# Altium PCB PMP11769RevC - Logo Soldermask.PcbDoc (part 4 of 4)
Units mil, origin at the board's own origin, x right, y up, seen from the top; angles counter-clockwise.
Board outline 7800 x 8510 mil, 4 copper layers (Top, Inner Top, Inner Bottom, Bottom), stack 33.235 mil thick; 451 components, 226 nets, 1199 pads, 1742 vias.
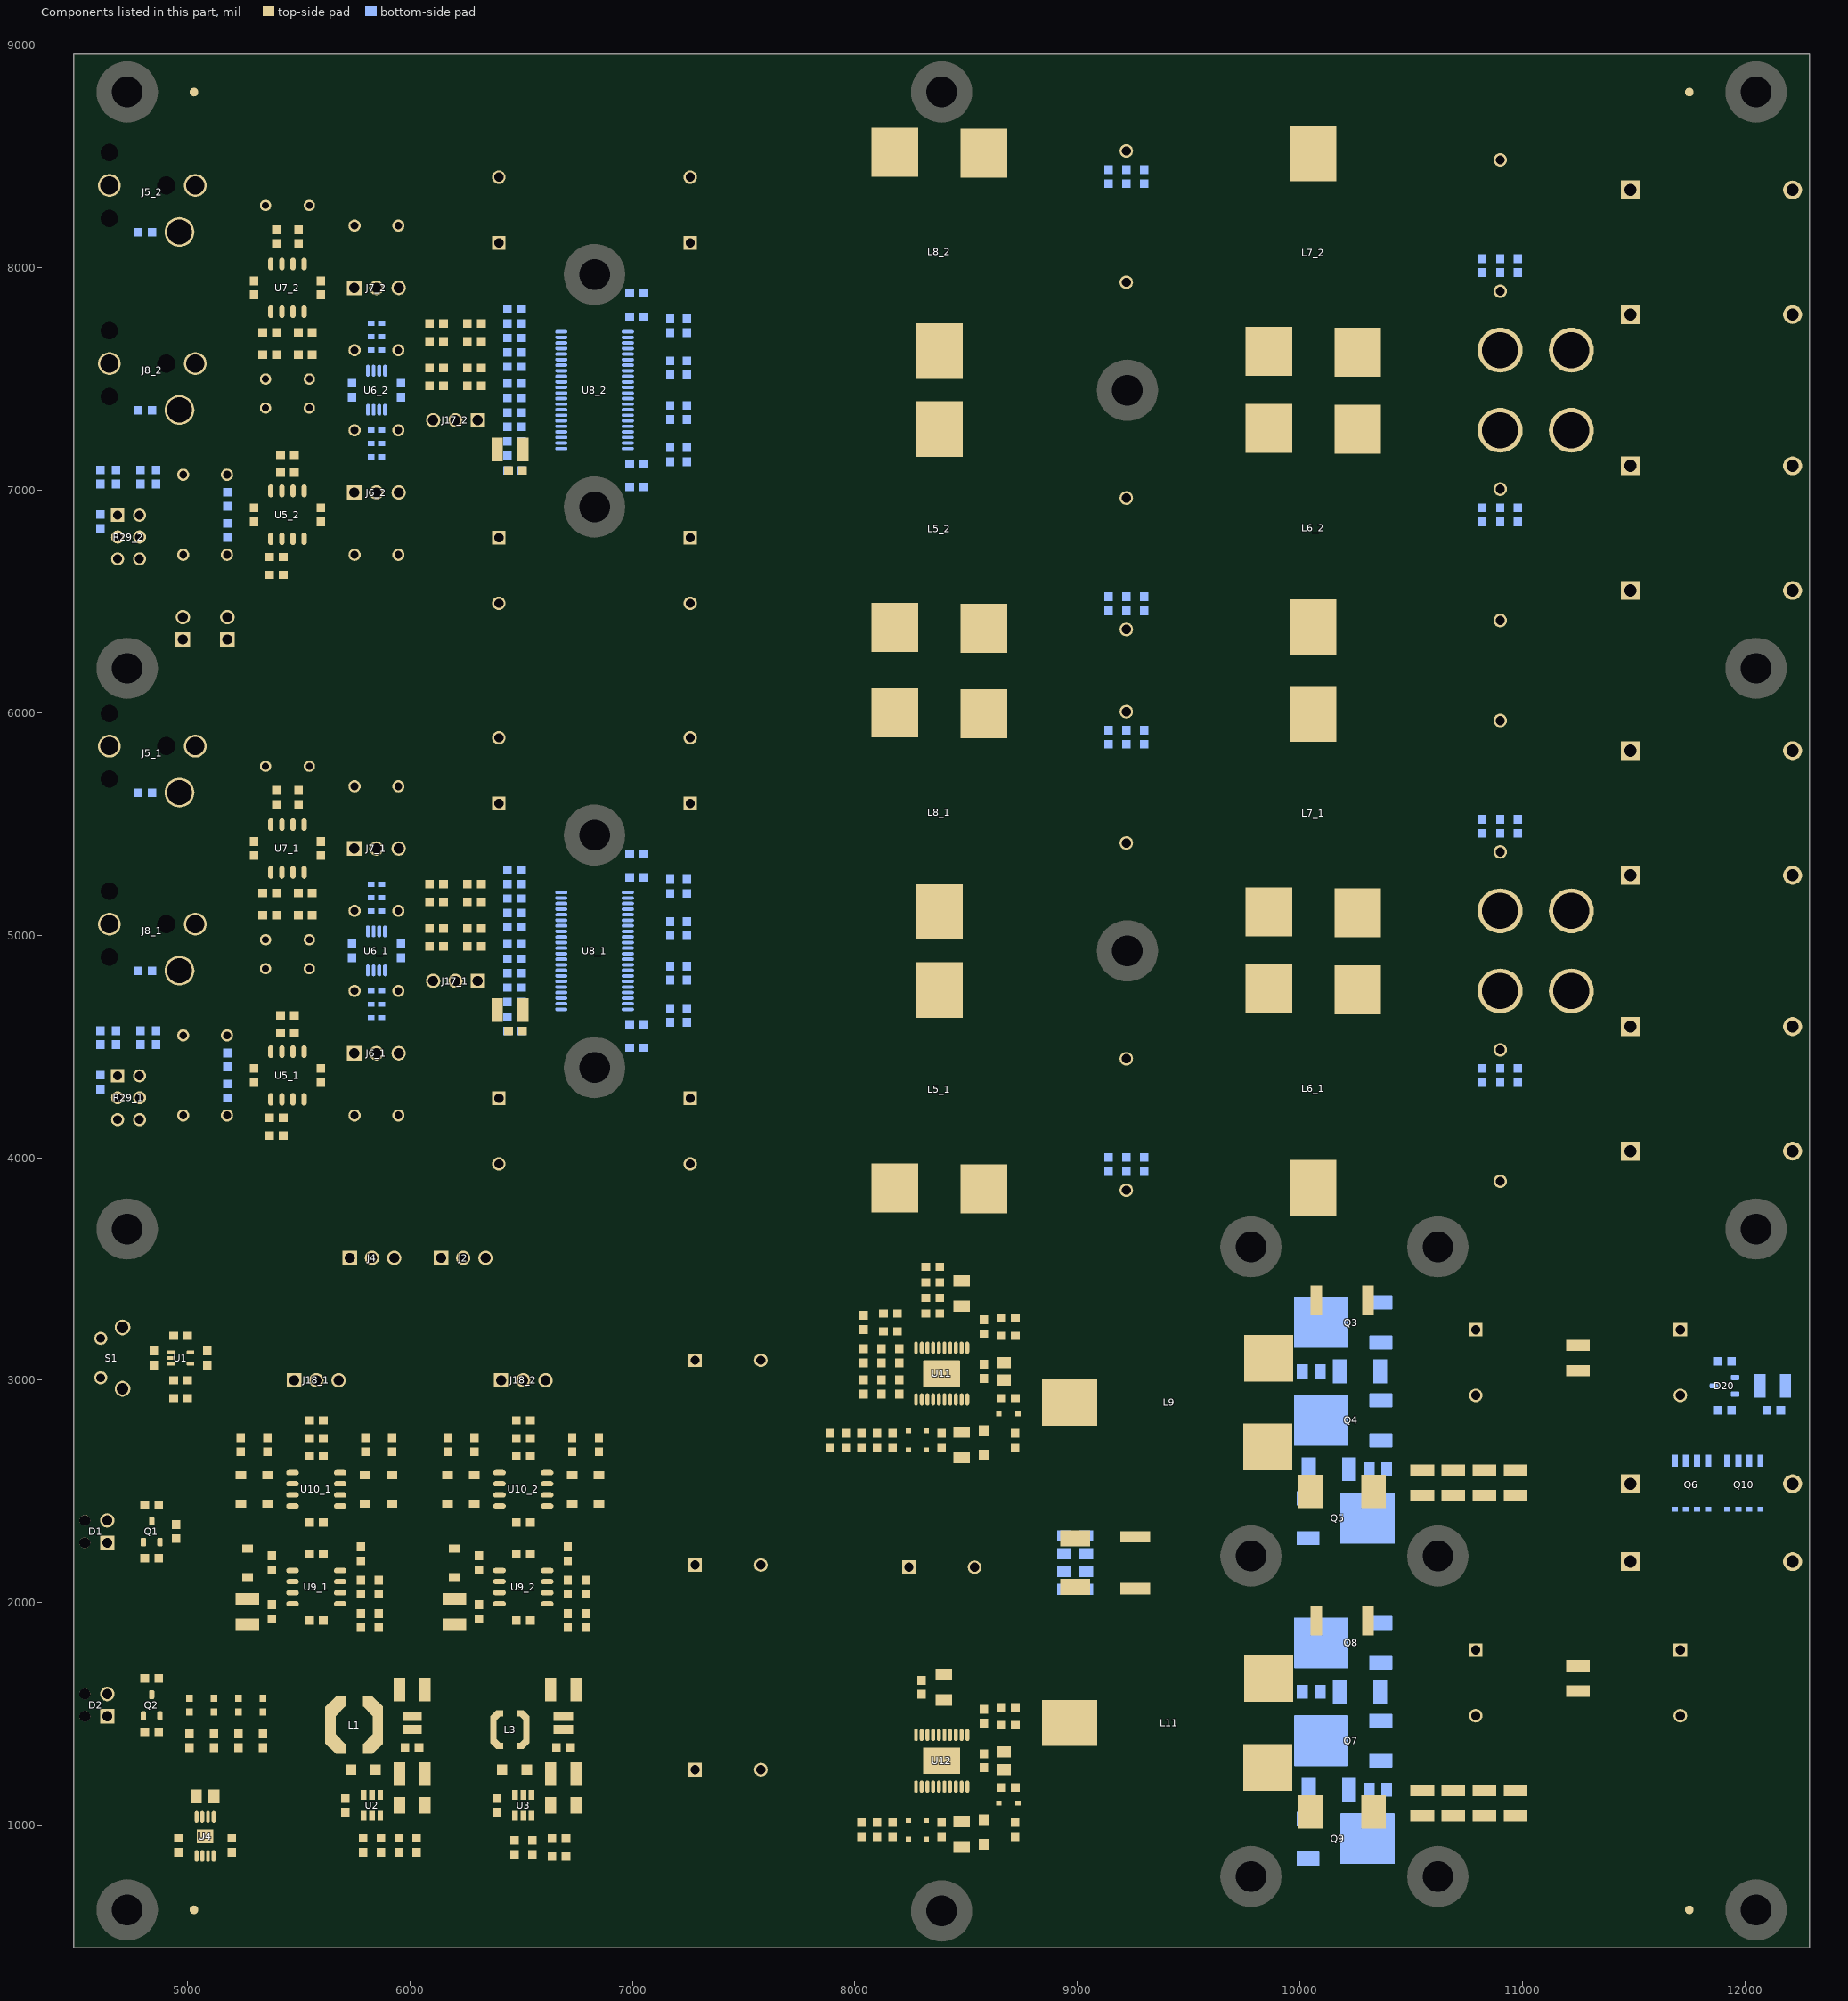
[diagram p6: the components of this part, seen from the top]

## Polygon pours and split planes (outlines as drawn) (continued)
+3V3 on Top "Top-No Net 24" (solid, pour order 446): 5050,1010 4990,1010 4990,1185 5070,1185 5070,1095 5050,1075
NetC16_1 on Top "Top-No Net 23" (solid, pour order 445): 5245,900 5110,900 5110,815 5245,815
+12V on Top "Top-No Net 23" (solid, pour order 447): 5075,900 4915,900 4915,815 5075,815
PVDD on Top "Top-No Net 22" (solid, pour order 513): 7050,3600 7810,3600 7810,770 7050,770
PVDD on Top "Top-No Net 22" (solid, pour order 498): 8810,2520 8810,1800 7200,1800 7200,2520
PVDD on Top "Top-No Net 21" (solid, pour order 461): 9590,2160 9590,2030 8790,2030 8790,2160
NetC95_2 on Top "Top-No Net 20" (solid, pour order 467): 8850,2200 9590,2200 9590,2440 8850,2440
GND on Top "Top-No Net 19" (solid, pour order 468): 11100,2200 11100,2070 9700,2070 9700,2200
GND on Top "Bottom-No Net 24" (solid, pour order 508): 7850,2560 7850,3600 9590,3600 9590,2560
VIN on Top "Top-No Net 14" (solid, pour order 493): 11890,3470 12290,3470 12290,1680 11890,1680
NetL11_2 on Top "Top-No Net 9" (solid, pour order 474): 10170,2030 9700,2030 9700,1520 10170,1520
SW-2 on Top "Top-No Net 10" (solid, pour order 484): 10170,1480 9700,1480 9700,770 10170,770
SW-1 on Top "Top-No Net 10" (solid, pour order 483): 10170,2920 9700,2920 9700,2240 10170,2240
NetL9_2 on Top "Top-No Net 9" (solid, pour order 473): 10170,3430 9700,3430 9700,2960 10170,2960
VIN on Top "Top-No Net 8" (solid, pour order 496): 12290,3600 12290,3120 10220,3120 10220,3600
NetC68_1_1 on Top "Bottom-No Net" (solid, remove dead copper, pour order 499): 12290,4950 12290,5530 10080,5530 10080,4950
NetC74_1_1 on Top "Bottom-No Net 1" (solid, remove dead copper, pour order 511): 12290,6120 8400,6120 8400,5570 12290,5570
NetC61_1_1 on Top "Bottom-No Net" (solid, remove dead copper, pour order 500): 12290,4330 12290,4910 10080,4910 10080,4330
NetC41_1_1 on Top "Bottom-No Net 1" (solid, remove dead copper, pour order 509): 12290,3750 8400,3750 8400,4290 12290,4290
NetC55_1_2 on Top "Top-No Net 2" (solid, remove dead copper, pour order 486): 8360,3750 7640,3750 7640,4290 8360,4290
NetC65_1_1 on Top "Top-No Net 2" (solid, remove dead copper, pour order 488): 8360,5570 7640,5570 7640,6120 8360,6120
NetC64_1_1 on Top "Top-No Net 3" (solid, remove dead copper, pour order 503): 7690,4950 10040,4950 10040,5530 7690,5530
NetC54_1_2 on Top "Top-No Net 3" (solid, remove dead copper, pour order 504): 7690,4330 10040,4330 10040,4910 7690,4910
NetC64_1_1 on Top "Top-No Net" (solid, remove dead copper, pour order 437): 7030,5000 7020,4990 7020,4950 7030,4940 7100,4940 7100,5000
NetC54_1_2 on Top "Top-No Net" (solid, remove dead copper, pour order 439): 7030,4920 7020,4910 7020,4870 7030,4860 7100,4860 7100,4920
NetC64_1_1 on Top "Top-No Net 4" (solid, pour order 469): 7095,5000 7105,5000 7125,5000 7655,5530 7695,5530 7695,4950 7125,4950 7115,4940 7095,4940
NetC54_1_2 on Top "Top-No Net 4" (solid, pour order 471): 7095,4860 7105,4860 7125,4860 7655,4330 7695,4330 7695,4910 7125,4910 7115,4920 7095,4920
NetC65_1_1 on Top "Top-No Net 6" (solid, pour order 480): 7090,5050 7125,5050 7645,5570 7645,6120 7320,6120 7320,5550 7090,5320
NetC55_1_2 on Top "Top-No Net 6" (solid, pour order 479): 7090,4810 7125,4810 7645,4290 7645,3750 7320,3750 7320,4310 7090,4540
NetC55_1_2 on Top "Top-No Net 1" (solid, pour order 451): 7020,4810 7020,4530 7100,4530 7100,4810
NetC65_1_1 on Top "Top-No Net 1" (solid, pour order 450): 7020,5330 7020,5050 7100,5050 7100,5330
GND on Top "Top-No Net 5" (solid, pour order 492): 6045,5750 6045,6120 7295,6120 7295,5750
GND on Top "Top-No Net 5" (solid, pour order 490): 6045,3750 6045,4110 7295,4110 7295,3750
GND on Top "Top-No Net 7" (solid, remove dead copper, pour order 515): 4490,6120 4490,3750 6325,3750 6325,4340 6942.5,4340 6942.5,5515 6325,5515 6325,6120
NetC95_2 on Top "Top-No Net 11" (solid, pour order 475): 11040,2240 11040,2520 10450,2520 10450,2600 10220,2600 10220,2240
VIN on Top "Top-No Net 8" (solid, pour order 494): 12285,2030 12285,1680 10220,1680 10220,2030
GND on Top "Top-No Net 12" (solid, pour order 497): 10220,1640 10220,1200 10470,1200 10470,1120 12290,1120 12290,1640
NetC95_2 on Top "Top-No Net 11" (solid, pour order 476): 11040,770 11040,1080 10450,1080 10450,1160 10220,1160 10220,770
GND on Top "Top-No Net 15" (solid, pour order 495): 10220,3080 10220,2640 10470,2640 10470,2560 11330,2560 11330,2620 11870,2620 11870,3080
GND on Top "Bottom-No Net 24" (solid, pour order 507): 7850,770 7850,1760 9590,1760 9590,770
GND on Top "Top-No Net 16" (solid, pour order 477): 11080,770 11080,1140 12290,1140 12290,1030 11710,1030 11710,770
VIN on Top "Top-No Net 17" (solid, pour order 460): 10240,3600 10240,3440 9700,3440 9700,3600
GND on Top "Top-No Net 18" (solid, pour order 462): 11080,2620 11080,2070 11330,2070 11330,2620
VIN on Top "Top-No Net 13" (solid, pour order 482): 11360,2580 11910,2580 11910,2010 11360,2010
VIN on Bottom "Bottom-No Net 5" (solid, pour order 621): 12130,2830 11990,2830 11990,3050 12130,3050
PVDD on Bottom "Bottom-No Net 2" (solid, remove dead copper, pour order 625): 6950,7508.7 7020,7508.7 7031.3,7520 7115,7520 7150,7555 7320,7555 7320,7735 7125,7735 7125,7700 7125,7603.7 7091.3,7570 6950,7570
GND on Bottom "Bottom-No Net 11" (solid, remove dead copper, pour order 647): 6025,8640 7335,8638.89 7335,6270 4490,6270 4490,8640
GND on Bottom "Bottom-No Net 9" (solid, remove dead copper, pour order 651): 7315,8640 7315,6270 12290,6270 12290,8640
PVDD on Bottom "Bottom-No Net 2" (solid, remove dead copper, pour order 626): 6950,7395 7015,7395 7030,7380 7120,7380 7155,7345 7320,7345 7320,7165 7125,7165 7125,7200 7125,7295 7090,7330 6950,7330
NetC64_2_1 on Bottom "Bottom-No Net 3" (solid, remove dead copper, pour order 603): 6950,7495 6950,7480 7025,7480 7035,7470 7090,7470 7100,7480 7100,7500 7090,7510 7035,7510 7020,7495
NetC54_2_2 on Bottom "Bottom-No Net 3" (solid, remove dead copper, pour order 602): 6950,7405 6950,7420 7025,7420 7035,7430 7090,7430 7100,7420 7100,7400 7090,7390 7036.04,7390 7021.04,7405
NetC55_2_2 on Bottom "Bottom-No Net 4" (solid, remove dead copper, pour order 605): 6950,7320 6950,7280 7087.5,7280 7097.5,7290 7097.5,7310 7087.5,7320
NetC65_2_1 on Bottom "Bottom-No Net 4" (solid, remove dead copper, pour order 608): 6950,7620 6950,7580 7087.5,7580 7097.5,7590 7097.5,7610 7087.5,7620
PVDD on Bottom "Bottom-No Net 31" (solid, pour order 623): 8805,2025 8805,2160 8885,2160 8885,2105 8900,2090 9080,2090 9093.07,2101.58 9095,2105 9095,2100 9095,2160 9175,2160 9175,2025
NetC95_2 on Bottom "Bottom-No Net 30" (solid, pour order 622): 9085,2270 8890,2270 8890,2425 9090,2425 9090,2270
GND on Bottom "Bottom-No Net 29" (solid, pour order 628): 5380,3580 5380,3770 5655,3770 5660,3775 5660,3580
GND on Bottom "Top-No Net 34" (solid, pour order 649): 4490,3600 7010,3600 7010,770 4490,770
NetC10_2 on Bottom "Bottom-No Net 28" (solid, pour order 629): 6450,960 6600,960 6600,1315 6450,1315
GND on Bottom "Bottom-No Net 27" (solid, pour order 638): 7930,6310 6050,6310 6050,6080 7930,6080
GND on Bottom "Bottom-No Net 24" (solid, pour order 645): 7850,2500 7850,3600 9660,3600 9660,2500
GND on Bottom "Bottom-No Net 20" (solid, pour order 644): 12290,2600 10470,2600 10470,2690 10300,2690 10300,3600 12290,3600
NetJ20_1 on Bottom "Bottom-No Net 19" (solid, pour order 631): 12290,2580 12290,2350 11425,2350 11425,2580
NetD17_2 on Bottom "Bottom-No Net 18" (solid, pour order 613): 10460,3390 10460,3310 10300,3310 10300,3390
NetD18_2 on Bottom "Bottom-No Net 18" (solid, pour order 612): 10460,2950 10460,2870 10300,2870 10300,2950
NetD19_2 on Bottom "Bottom-No Net 18" (solid, pour order 611): 10100,2330 10100,2250 9940,2250 9940,2330
NetC111_1 on Bottom "Bottom-No Net 14" (solid, pour order 619): 10340,1100 10180,1100 10180,1220 10340,1220
NetC95_2 on Bottom "Bottom-No Net 17" (solid, pour order 615): 10360,1220 10450,1220 10450,1060 10360,1060
NetC116_2 on Bottom "Bottom-No Net 14" (solid, pour order 618): 10220,1550 10060,1550 10060,1670 10220,1670
NetC95_1 on Bottom "Bottom-No Net 14" (solid, pour order 620): 10340,2540 10160,2540 10160,2660 10340,2660
NetC96_2 on Bottom "Bottom-No Net 14" (solid, pour order 617): 10220,2980 10060,2980 10060,3100 10220,3100
NetC65_1_1 on Bottom "Bottom-No Net 4" (solid, remove dead copper, pour order 607): 6950,5100 6950,5060 7087.5,5060 7097.5,5070 7097.5,5090 7087.5,5100
NetC55_1_2 on Bottom "Bottom-No Net 4" (solid, remove dead copper, pour order 606): 6950,4800 6950,4760 7087.5,4760 7097.5,4770 7097.5,4790 7087.5,4800
NetC54_1_2 on Bottom "Bottom-No Net 3" (solid, remove dead copper, pour order 601): 6950,4885 6950,4900 7025,4900 7035,4910 7090,4910 7100,4900 7100,4880 7090,4870 7036.04,4870 7021.04,4885
NetC64_1_1 on Bottom "Bottom-No Net 3" (solid, remove dead copper, pour order 604): 6950,4975 6950,4960 7025,4960 7035,4950 7090,4950 7100,4960 7100,4980 7090,4990 7035,4990 7020,4975
PVDD on Bottom "Bottom-No Net 2" (solid, remove dead copper, pour order 627): 6950,4875 7015,4875 7030,4860 7115,4860 7150,4825 7320,4825 7320,4645 7125,4645 7125,4680 7125,4775 7090,4810 6950,4810
GND on Bottom "Bottom-No Net 9" (solid, remove dead copper, pour order 650): 7315,6120 7315,3750 12290,3750 12290,6120
GND on Bottom "Bottom-No Net 11" (solid, remove dead copper, pour order 648): 6025,6120 7335,6118.89 7335,3750 4490,3750 4490,6120
SW-1 on Bottom "Bottom-No Net 15" (solid, pour order 640): 10270,3470 10270,2690 10120,2690 10120,2240 9700,2240 9700,3470
NetC95_2 on Bottom "Bottom-No Net 16" (solid, pour order 633): 10160,2240 11040,2240 11040,2520 10160,2520
NetC95_2 on Bottom "Bottom-No Net 17" (solid, pour order 616): 10360,2660 10450,2660 10450,2500 10360,2500
NetC95_2 on Bottom "Bottom-No Net 16" (solid, pour order 635): 10160,770 11040,770 11040,1080 10160,1080
NetD24_2 on Bottom "Bottom-No Net 18" (solid, pour order 614): 10100,890 10100,810 9940,810 9940,890
SW-2 on Bottom "Bottom-No Net 15" (solid, pour order 639): 10270,1940 10270,1250 10120,1250 10120,770 9700,770 9700,1940
NetD23_2 on Bottom "Bottom-No Net 18" (solid, pour order 610): 10460,1950 10460,1870 10300,1870 10300,1950
NetD22_2 on Bottom "Bottom-No Net 18" (solid, pour order 609): 10460,1510 10460,1430 10300,1430 10300,1510
GND on Bottom "Bottom-No Net 20" (solid, pour order 641): 12290,1120 10470,1120 10470,1250 10300,1250 10300,2010 12290,2010
GND on Bottom "Bottom-No Net 21" (solid, pour order 632): 11400,2620 11060,2620 11060,1990 11400,1990
GND on Bottom "Bottom-No Net 23" (solid, pour order 637): 11080,2220 11080,1980 9620,1980 9620,2220
GND on Bottom "Bottom-No Net 24" (solid, pour order 643): 7850,770 7850,1820 9660,1820 9660,770
GND on Bottom "Bottom-No Net 25" (solid, pour order 630): 10330,3500 9700,3500 9700,3600 10330,3600
GND on Bottom "Bottom-No Net 25" (solid, pour order 636): 11710,770 11080,770 11080,1140 12290,1140 12290,1030 11710,1030
GND on Bottom "Bottom-No Net 26" (solid, pour order 642): 9660,2520 9660,1800 7200,1800 7200,2520
GND on Bottom "Bottom-No Net 27" (solid, pour order 646): 7810,3790 7050,3790 7050,770 7810,770
PVDD on Bottom "Bottom-No Net 2" (solid, remove dead copper, pour order 624): 6950,4988.7 7020,4988.7 7031.3,5000 7115,5000 7150,5035 7320,5035 7320,5215 7125,5215 7125,5180 7125,5083.7 7091.3,5050 6950,5050
VIN on Bottom "Bottom-No Net 22" (solid, pour order 634): 11425,2330 11425,2035 12290,2035 12290,2330
NetC55_2_2 on Inner Top "Top-No Net 2" (solid, remove dead copper, pour order 544): 8360,6270 7640,6270 7640,6810 8360,6810
NetC55_2_2 on Inner Top "Top-No Net 1" (solid, pour order 520): 7017.01,7330 7017.01,7050 7097.01,7050 7097.01,7330
NetC55_2_2 on Inner Top "Top-No Net 6" (solid, pour order 539): 7090,7330 7125,7330 7645,6810 7645,6270 7320,6270 7320,6830 7090,7060
NetC65_2_1 on Inner Top "Top-No Net 2" (solid, remove dead copper, pour order 545): 8360,8090 7640,8090 7640,8640 8360,8640
NetC65_2_1 on Inner Top "Top-No Net 6" (solid, pour order 541): 7090,7570 7125,7570 7645,8090 7645,8640 7320,8640 7320,8070 7090,7840
NetC54_2_2 on Inner Top "Inner Top-No Net 9" (solid, pour order 547): 8100,6860 7660,6860 7140,7380 7020,7380 7020,7430 8100,7430
NetC64_2_1 on Inner Top "Inner Top-No Net 9" (solid, pour order 550): 8100,8040 7660,8040 7140,7520 7020,7520 7020,7470 8100,7470
NetC64_2_1 on Inner Top "Top-No Net 3" (solid, pour order 560): 8080,7480 10030,7480 10030,8040 8080,8040
NetC54_2_2 on Inner Top "Top-No Net 3" (solid, pour order 559): 8080,6860 10030,6860 10030,7420 8080,7420
NetC74_2_1 on Inner Top "Bottom-No Net 1" (solid, remove dead copper, pour order 569): 12290,8100 8410,8100 8410,8640 12290,8640
NetC41_2_1 on Inner Top "Bottom-No Net 1" (solid, remove dead copper, pour order 566): 12290,6270 8410,6270 8410,6800 12290,6800
NetC68_2_1 on Inner Top "Bottom-No Net" (solid, remove dead copper, pour order 563): 12290,7480 12290,8040 10080,8040 10080,7480
NetC61_2_1 on Inner Top "Bottom-No Net" (solid, remove dead copper, pour order 562): 12290,6860 12290,7420 10090,7420 10090,6860
NetC65_2_1 on Inner Top "Top-No Net 1" (solid, pour order 519): 7020.54,7849.4 7020.54,7569.4 7100.54,7569.4 7100.54,7849.4
PVDD on Inner Top "Inner Top-No Net 16" (solid, remove dead copper, pour order 525): 7295,6670 7295,6820 6365,6820 6365,6670
PVDD on Inner Top "Inner Top-No Net 16" (solid, remove dead copper, pour order 527): 7295,8075 7295,8225 6365,8225 6365,8075
PVDD on Inner Top "Inner Top-No Net 16" (solid, remove dead copper, pour order 524): 7295,5555 7295,5705 6365,5705 6365,5555
PVDD on Inner Top "Inner Top-No Net 16" (solid, remove dead copper, pour order 526): 7295,4150 7295,4300 6365,4300 6365,4150
NetC65_1_1 on Inner Top "Top-No Net 1" (solid, pour order 518): 7020.54,5329.4 7020.54,5049.4 7100.54,5049.4 7100.54,5329.4
PVDD on Inner Top "Inner Top-No Net 14" (solid, pour order 570): 7050,3600 7810,3600 7810,770 7050,770
PVDD on Inner Top "Inner Top-No Net 13" (solid, pour order 565): 9150,1800 7100,1800 7100,2520 8810,2520 8810,2160 9150,2160
NetC95_2 on Inner Top "Inner Top-No Net 12" (solid, pour order 528): 8850,2480 8850,2200 9390,2200 9390,2480
VIN on Inner Top "Inner Top-No Net 8" (solid, pour order 551): 11890,1680 12290,1680 12290,3470 11890,3470
SW-1 on Inner Top "Inner Top-No Net 7" (solid, pour order 530): 9700,2500 10170,2500 10170,2920 9700,2920
GND on Inner Top "Inner Top-No Net 6" (solid, pour order 521): 10570,3310 10570,3050 10220,3050 10220,3310
VIN on Inner Top "Inner Top-No Net" (solid, pour order 555): 10220,3600 10220,3390 10600,3390 10600,3120 12290,3120 12290,3600
VIN on Inner Top "Inner Top-No Net 3" (solid, pour order 534): 11360,2580 11910,2580 11910,2110 11360,2110
NetC95_2 on Inner Top "Inner Top-No Net 2" (solid, pour order 533): 10220,2600 10450,2600 10450,2520 11040,2520 11040,2240 10223.54,2240 10220,2243.54
NetL9_2 on Inner Top "Inner Top-No Net 1" (solid, pour order 540): 10170,3600 10170,2960 9700,2960 9700,3600
NetC61_1_1 on Inner Top "Bottom-No Net" (solid, remove dead copper, pour order 561): 12290,4340 12290,4900 10090,4900 10090,4340
NetC68_1_1 on Inner Top "Bottom-No Net" (solid, remove dead copper, pour order 564): 12290,4960 12290,5520 10080,5520 10080,4960
NetC41_1_1 on Inner Top "Bottom-No Net 1" (solid, remove dead copper, pour order 567): 12290,3750 8410,3750 8410,4280 12290,4280
NetC74_1_1 on Inner Top "Bottom-No Net 1" (solid, remove dead copper, pour order 568): 12290,5580 8410,5580 8410,6120 12290,6120
NetC54_1_2 on Inner Top "Top-No Net 3" (solid, pour order 558): 8080,4340 10030,4340 10030,4900 8080,4900
NetC64_1_1 on Inner Top "Top-No Net 3" (solid, pour order 557): 8080,4960 10030,4960 10030,5520 8080,5520
NetL11_2 on Inner Top "Inner Top-No Net 1" (solid, pour order 536): 10170,2130 10170,1520 9700,1520 9700,2130
SW-2 on Inner Top "Inner Top-No Net 7" (solid, pour order 529): 9700,1060 10170,1060 10170,1480 9700,1480
VIN on Inner Top "Inner Top-No Net" (solid, pour order 553): 10220,2130 10220,1950 10600,1950 10600,1680 12290,1680 12290,2130
NetC95_2 on Inner Top "Inner Top-No Net 2" (solid, pour order 535): 10220,1160 10450,1160 10450,1080 11040,1080 11040,770 10220,770
GND on Inner Top "Inner Top-No Net 5" (solid, pour order 556): 10220,1640 10220,1200 10470,1200 10470,1120 12290,1120 12290,1640
GND on Inner Top "Inner Top-No Net 6" (solid, pour order 522): 10570,1870 10570,1610 10220,1610 10220,1870
NetC64_1_1 on Inner Top "Inner Top-No Net 9" (solid, pour order 549): 8100,5520 7660,5520 7140,5000 7020,5000 7020,4950 8100,4950
NetC54_1_2 on Inner Top "Inner Top-No Net 9" (solid, pour order 548): 8100,4340 7660,4340 7140,4860 7020,4860 7020,4910 8100,4910
NetC65_1_1 on Inner Top "Top-No Net 6" (solid, pour order 542): 7090,5050 7125,5050 7645,5570 7645,6120 7320,6120 7320,5550 7090,5320
NetC65_1_1 on Inner Top "Top-No Net 2" (solid, remove dead copper, pour order 546): 8360,5570 7640,5570 7640,6120 8360,6120
NetC55_1_2 on Inner Top "Top-No Net 6" (solid, pour order 538): 7090,4810 7125,4810 7645,4290 7645,3750 7320,3750 7320,4310 7090,4540
NetC55_1_2 on Inner Top "Top-No Net 1" (solid, pour order 517): 7017.01,4810 7017.01,4530 7097.01,4530 7097.01,4810
NetC55_1_2 on Inner Top "Top-No Net 2" (solid, remove dead copper, pour order 543): 8360,3750 7640,3750 7640,4290 8360,4290
GND on Inner Top "Top-No Net 15" (solid, pour order 552): 10220,3080 10220,2640 10470,2640 10470,2560 11330,2560 11330,2620 11830,2620 11830,3080
NetC95_2 on Inner Top "Inner Top-No Net 10" (solid, pour order 531): 10240,2480 9350,2480 9350,2240 10240,2240
NetC95_2 on Inner Top "Inner Top-No Net 10" (solid, pour order 532): 10240,1040 9350,1040 9350,770 10240,770
GND on Inner Top "Bottom-No Net 25" (solid, pour order 537): 11709.6,770 11080,770 11080,1140 12290,1140 12290,1030 11710,1030
GND on Inner Top "Top-No Net 18" (solid, pour order 523): 11080,2620 11080,2240 11330,2240 11330,2620
NetC95_2 on Inner Top "Inner Top-No Net 11" (solid, pour order 554): 9660,2480 9660,770 9175,770 9175,2480
GND on Inner Bottom "Inner Bottom-No Net 11" (solid, pour order 571): 7330,4840 7330,5020 7005,5020 7005,4840
GND on Inner Bottom "Inner Bottom-No Net 11" (solid, pour order 572): 7330,7360 7330,7540 7005,7540 7005,7360
GND on Inner Bottom "Inner Bottom-No Net 10" (solid, pour order 596): 7025,5705 7025,4150 6540,4150 6540,5705
GND on Inner Bottom "Inner Bottom-No Net 10" (solid, pour order 595): 7025,8225 7025,6670 6540,6670 6540,8225
NetC41_2_1 on Inner Bottom "Inner Bottom-No Net" (solid, pour order 594): 10760,7410 11040,7410 11040,6790 11680,6790 11680,6270 10760,6270
NetC74_2_1 on Inner Bottom "Inner Bottom-No Net" (solid, pour order 589): 11080,7490 11360,7490 11360,8110 11680,8110 11680,8630 11080,8630
GND on Inner Bottom "Inner Bottom-No Net 9" (solid, pour order 579): 7810,2900 7490,2900 7490,3600 7810,3600
PVDD on Inner Bottom "Inner Top-No Net 15" (solid, remove dead copper, pour order 600): 7046.2,8225 7046.2,2981.42 7450,2981.42 7450,3640 7810,3640 7810,8225
GND on Inner Bottom "Inner Bottom-No Net 8" (solid, pour order 588): 8460,1800 8460,2220 9330,2220 9410,2220 9410,1800
GND on Inner Bottom "Inner Bottom-No Net 7" (solid, pour order 598): 7050,2940 7810,2940 7810,770 7050,770
GND on Inner Bottom "Inner Bottom-No Net 5" (solid, pour order 574): 10310,3210 9400,3210 9400,3410 10220,3410 10220,3310 10310,3310
VIN on Inner Bottom "Top-No Net 14" (solid, pour order 587): 11890,3470 12290,3470 12290,2620 11890,2620
GND on Inner Bottom "Inner Bottom-No Net 3" (solid, pour order 573): 10300,3310 10570,3310 10570,3050 10300,3050
VIN on Inner Bottom "Inner Bottom-No Net 1" (solid, pour order 592): 10330,3470 10330,3390 10600,3390 10600,3120 12290,3120 12290,3470
GND on Inner Bottom "Inner Top-No Net 4" (solid, pour order 591): 10300,3080 10300,2640 10470,2640 10470,2560 11400,2560 11400,3080
NetC95_2 on Inner Bottom "Top-No Net 11" (solid, pour order 582): 11040,2240 11040,2520 10450,2520 10450,2600 10220,2600 10220,2240
SW-1 on Inner Bottom "Bottom-No Net 15" (solid, pour order 586): 10220,3150 10220,2690 10170,2690 10170,2500 9700,2500 9700,3150
NetC74_1_1 on Inner Bottom "Inner Bottom-No Net" (solid, pour order 590): 11080,4970 11360,4970 11360,5590 11680,5590 11680,6110 11080,6110
NetC41_1_1 on Inner Bottom "Inner Bottom-No Net" (solid, pour order 593): 10760,4890 11040,4890 11040,4270 11680,4270 11680,3750 10760,3750
SW-2 on Inner Bottom "Bottom-No Net 15" (solid, pour order 585): 10220,1710 10220,1250 10170,1250 10170,1060 9700,1060 9700,1482.17 9927.83,1710
NetC95_2 on Inner Bottom "Top-No Net 11" (solid, pour order 584): 11040,770 11040,1080 10450,1080 10450,1160 10220,1160 10220,770
GND on Inner Bottom "Inner Top-No Net 4" (solid, pour order 599): 10300,2010 10300,1200 10470,1200 10470,1120 12290,1120 12290,2010
GND on Inner Bottom "Inner Bottom-No Net 4" (solid, pour order 576): 11060,2620 11400,2620 11400,2010 11060,2010
GND on Inner Bottom "Bottom-No Net 23" (solid, pour order 597): 11080,2220 11080,1760 9370,1760 9370,2220
NetC95_2 on Inner Bottom "Inner Top-No Net 10" (solid, pour order 581): 10240,1040 9370,1040 9370,770 10240,770
NetC95_2 on Inner Bottom "Inner Top-No Net 10" (solid, pour order 578): 10240,2480 9370,2480 9370,2240 10240,2240
GND on Inner Bottom "Inner Bottom-No Net 6" (solid, pour order 575): 9370,1780 9370,1460 9960,1460 9960,1780
GND on Inner Bottom "Inner Bottom-No Net 2" (solid, pour order 580): 11870,3080 11870,2620 11380,2620 11380,3080
NetJ20_1 on Inner Bottom "Bottom-No Net 19" (solid, pour order 577): 12290,2580.45 12290,2340 11425,2340 11425,2580.45
VIN on Inner Bottom "Bottom-No Net 22" (solid, pour order 583): 11425,2330 11425,2035 12290,2035 12290,2330

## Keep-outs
Keep-Out Layer:
  text ".Layer_Name" at 577,-858.49 h60

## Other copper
Top:
  text "1" at 11790,850 h100
  text ".Layer_Name" at 577,-858.49 h60
Inner Top:
  text "2" at 11890,850 h100
Inner Bottom:
  text "3" at 12020,850 h100
Bottom:
  text "4" at 12150,850 h100
  text ".Layer_Name" at 577,-858.49 h60

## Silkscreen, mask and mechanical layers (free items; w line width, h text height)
Top Overlay:
  circle w10: c5460,8560 r5
  circle w10: c5575,8560 r5
  circle w10: c6533,3220 r3
  circle w10: c6449,3220 r3
  circle w10: c5623,3220 r3
  circle w10: c5540,3220 r3
  circle w10: c5835,3350 r5
  circle w10: c5640,3350 r5
  circle w10: c5575,6040 r5
  circle w10: c5460,6040 r5
  circle w10: c5575,8560 r5
  circle w10: c5460,8560 r5
  rectangle: 11420,790 11580,900
  lines w10: 10900,4875 10900,4985 ; 11220,7395 11220,7505 ; 11225,4875 11225,4985 ; 11225,7395 11225,7505 ; 10900,7395 10900,7505 10900,7395
  text "Amplifier 2" at 5180,8490 h70
  text "S" at 5735,7800 h40
  text "M" at 5940,7800 h40
  text "OPEN:  Stereo" at 11475,7510 h50
  text "SHORT: Mono" at 11475,7340 h50
  text "S" at 6090,7200 h40
  text "M" at 6290,7200 h40
  text "S" at 5735,6880 h40
  text "M" at 5940,6880 h40
  text "OPEN:  4-Channel" at 5260,6410 h50
  text "SHORT: 2-Channel" at 5260,6300 h50
  text "Amplifier 1" at 5180,5970 h70
  text "S" at 5735,5280 h40
  text "M" at 5940,5280 h40
  text "OPEN:  Stereo" at 11475,4990 h50
  text "SHORT: Mono" at 11475,4820 h50
  text "S" at 6090,4680 h40
  text "M" at 6290,4680 h40
  text "S" at 5735,4360 h40
  text "M" at 5940,4360 h40
  text "M" at 5715,3440 h40
  text "P" at 5815,3440 h40
  text "P" at 5915,3440 h40
  text "M" at 6125,3440 h40
  text "M" at 6225,3440 h40
  text "P" at 6325,3440 h40
  text "Clipping Detector" at 5500,3280 h70
  text "Amplifier 1" at 5340,3170 h50
  text "Amplifier 2" at 6250,3170 h50
  text "RESET" at 4555,2895 h50 r270
  text "L" at 5465,2890 h40
  text "R" at 5665,2890 h40
  text "L" at 6395,2890 h40
  text "R" at 6600,2890 h40
  text "-" at 12090,2740 h200
  text "FAULT" at 4565,2160 h50 r270
  text "+" at 12090,1790 h200
  text "+3.3V" at 5030,1640 h40 r90
  text "-12V" at 5140,1640 h40 r90
  text "+12V" at 5250,1640 h40 r90
  text "+36V" at 5358.72,1640.48 h40 r90
  text "CLIP" at 4565,1380 h50 r270
  text "PMP11769" at 11140,940 h70
  text "Rev." at 11140,810 h70
  text ".Layer_Name" at 577,-858.49 h60
Bottom Overlay:
  text ".Layer_Name" at 577,-858.49 h60
Top Paste:
  text ".Layer_Name" at 577,-858.49 h60
Bottom Paste:
  text ".Layer_Name" at 577,-858.49 h60
Top Solder:
  text ".Layer_Name" at 577,-858.49 h60
  text ".Layer_Name" at 577,-858.49 h60
Bottom Solder:
  drawing of 4273 lines, arcs and shapes, not listed
  text ".Layer_Name" at 577,-858.49 h60
Drill Guide:
  text ".Layer_Name" at 577,-858.49 h60
Mechanical 1:
  lines w10: 4465,425 4465,8985 12315,8985 12315,425 4465,425
  text ".Layer_Name" at 577,-858.49 h60
Mechanical 2:
  text ".Layer_Name" at 577,-858.49 h60
Mechanical 3:
  text ".Layer_Name" at 577,-858.49 h60
Mechanical 4:
  text ".Layer_Name" at 577,-858.49 h60
Mechanical 5:
  lines w10: -292,-930.17 6308,-930.17 ; -292,-726.83 6310,-726.83 ; -292,-523.5 -292,-1133.5 3713,-1133.5 6310,-1133.5 6310,-523.5 -291.5,-523.5 -291.5,-1133.5 1284,-1133.5 ; 2173,-1133.5 2173,-523.5 ; 3440,-726.83 3440,-523.5 ; 4280,-726.83 4280,-523.5 ; 4902,-1140 4902,-937.17
  text "PCB VIEWED FROM TOP SIDE" at -228.5,-655.67 h60
  text "BOARD #:" at 2248,-655.67 h60
  text ".PRJ_Number" at 2793.5,-655.67 h60
  text "REV:" at 3638,-655.67 h60
  text ".PCB_Rev" at 3929.5,-655.67 h60
  text "SVN REV:" at 4476,-655.67 h60
  text ".VersionControl_RevNumber" at 4982,-655.67 h60
  text "IGNORE ->" at -228.5,-858.49 h60
  text "PLOT NAME =" at -228.5,-1064.34 h60
  text ".plot_File_Name" at 577,-1064.34 h60
  text "GENERATED    :" at 2250,-1064.34 h60
  text ".Print_Date" at 3119.5,-1064.34 h60
  text ".Print_Time" at 3848.5,-1064.34 h60
  text "TEXAS INSTRUMENTS" at 5113,-1064.34 h60
Mechanical 6:
  lines w10: -292.5,-727.33 6309.5,-727.33 ; -290.5,-930.67 6309.5,-930.67 ; 1115.5,-1140.5 1115.5,-937.67 ; 1737.5,-727.33 1737.5,-524 ; 2577.5,-727.33 2577.5,-524 ; 3844.5,-1134 3844.5,-524 ; 4490,540 4490,3940 ; 4733.5,-1134 6309,-1134 6309,-524 -292.5,-524 -292.5,-1134 2304.5,-1134 6309.5,-1134 6309.5,-524
  text ".VersionControl_RevNumber" at 1035.5,-656.17 h60
  text "SVN REV:" at 1541.5,-656.17 h60
  text ".PCB_Rev" at 2088,-656.17 h60
  text "REV:" at 2379.5,-656.17 h60
  text ".PRJ_Number" at 3224,-656.17 h60
  text "BOARD #:" at 3769.5,-656.17 h60
  text "PCB VIEWED FROM BOTTOM SIDE" at 6246,-656.17 h60
  text "IGNORE ->" at 2547.85,-858.49 h60
  text "TEXAS INSTRUMENTS" at 904.5,-1064.84 h60
  text ".Print_Time" at 2169,-1064.84 h60
  text ".Print_Date" at 2898,-1064.84 h60
  text "GENERATED    :" at 3767.5,-1064.84 h60
  text ".plot_File_Name" at 5440.5,-1064.84 h60
  text "PLOT NAME =" at 6246,-1064.84 h60
Mechanical 9:
  lines w10: -491.5,1041.5 -291.5,1041.5 ; -491.5,5791.5 -291.5,5791.5 ; 2008.5,-1333.5 2008.5,-1133.5 ; 2008.5,10450 2008.5,10650 ; 4480,10450 4480,10650 ; 4508.5,-1333.5 4508.5,-1133.5 ; 6321,-1133.5 6321,-523.5 11303.5,-523.5 ; 6998.5,-1333.5 6998.5,-1133.5 ; 7000,10436.5 7000,10636.5 ; 7000,10450 7000,10650 ; 7008.5,-1333.5 7008.5,-1133.5 ; 9498.5,-1333.5 9498.5,-1133.5 ; 9500,10436.5 9500,10636.5 ; 9508.5,-1333.5 9508.5,-1133.5 ; 11303.5,-1133.5 11303.5,-523.5 ; 11303.5,-823.5 14303.5,-823.5 ; 11998.5,-1333.5 11998.5,-1133.5 ; 12008.5,-1333.5 12008.5,-1133.5 ; 12010,10436.5 12010,10636.5 ; 12808.5,-1123.5 12808.5,-523.5 ; 14303.5,-523.5 11303.5,-523.5 ; 14308.5,66.5 14308.5,-1133.5 -291.5,-1133.5 -291.5,10450 14308.5,10450 ; 14310,-1133.5 14310,10450 ; -491.5,-1333.5 14508.5,-1333.5 14508.5,10650 -491.5,10650 -491.5,-1333.5
  text "1" at 739.84,10520 h70
  text "2" at 3235.5,10520 h70
  text "3" at 5710,10520 h70
  text "4" at 8223.01,10506.5 h70
  text "5" at 10722,10506.5 h70
  text "6" at 13237,10506.5 h70
  text "A" at -416.5,6893.5 h70
  text "D" at -416.5,-231.5 h70
  text "Texas Instruments (TI) and/or its licensors do not warrant the accuracy or completeness of this specification" at 6374,-605.34 h45
  text "ENGINEER:" at 11343.5,-613.5 h45
  text "LAYOUT BY:" at 12848.5,-613.5 h45
  text "or any information contained therein. TI and/or its licensors do not warrant that this design will meet" at 6329.01,-718 h45
  text ".PRJ_Engineer" at 11393.5,-768.49 h70
  text ".PCB_Layout" at 12899,-768.49 h70
  text "the specifications, will be suitable for your application or fit for any particular purpose, or will operate in" at 6329.01,-830.67 h45
  text ".Layer_Name" at 577,-858.49 h60
  text "ALTIUM DESIGNER VERSION:" at 12848.5,-923.5 h45
  text "an implementation. TI and/or its licensors do not warrant that the design is production worthy. You should" at 6329.01,-943.33 h45
  text "completely validate and test your design implementation to confirm the system functionality for your application." at 6374,-1056 h45
  text ".print_Scale" at 11393.5,-1056.83 h70
  text ".Application_BuildNumber" at 12899,-1056.83 h70
  text "1" at 739.84,-1263.5 h70
  text "2" at 3235.5,-1263.5 h70
  text "3" at 5724.84,-1263.5 h70
  text "4" at 8221.51,-1263.5 h70
  text "4" at 8231.51,-1263.5 h70
  text "5" at 10720.5,-1263.5 h70
  text "5" at 10730.5,-1263.5 h70
  text "6" at 13225.5,-1263.5 h70
  text "6" at 13235.5,-1263.5 h70
  text "6" at 12785.5,-1283.5 h70
Mechanical 10:
  text ".Layer_Name" at 577,-858.49 h60
Mechanical 11:
  lines w10: -292,-930.17 6308,-930.17 ; -292,-726.83 6310,-726.83 ; -292,-523.5 -292,-1133.5 3713,-1133.5 6310,-1133.5 6310,-523.5 -291.5,-523.5 -291.5,-1133.5 1284,-1133.5 ; 2173,-1133.5 2173,-523.5 ; 3440,-726.83 3440,-523.5 ; 4280,-726.83 4280,-523.5 ; 4902,-1140 4902,-937.17
  text "ALL ARTWORK VIEWED FROM TOP SIDE" at -228.5,-655.67 h60
  text "BOARD #:" at 2248,-655.67 h60
  text ".PRJ_Number" at 2793.5,-655.67 h60
  text "REV:" at 3638,-655.67 h60
  text ".PCB_Rev" at 3929.5,-655.67 h60
  text "SVN REV:" at 4476,-655.67 h60
  text ".VersionControl_RevNumber" at 4982,-655.67 h60
  text "LAYER NAME =" at -228.5,-858.49 h60
  text "PLOT NAME =" at -228.5,-1064.34 h60
  text ".plot_File_Name" at 577,-1064.34 h60
  text "GENERATED    :" at 2250,-1064.34 h60
  text ".Print_Date" at 3119.5,-1064.34 h60
  text ".Print_Time" at 3848.5,-1064.34 h60
  text "TEXAS INSTRUMENTS" at 5113,-1064.34 h60
Mechanical 12:
  text ".Layer_Name" at 577,-858.49 h60
Mechanical 13:
  text ".Layer_Name" at 577,-858.49 h60
Mechanical 14:
  text ".Layer_Name" at 577,-858.49 h60
Mechanical 15:
  text ".Layer_Name" at 577,-858.49 h60
Mechanical 16:
  text ".Layer_Name" at 577,-858.49 h60
Drill Drawing:
  text ".Layer_Name" at 577,-858.49 h60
